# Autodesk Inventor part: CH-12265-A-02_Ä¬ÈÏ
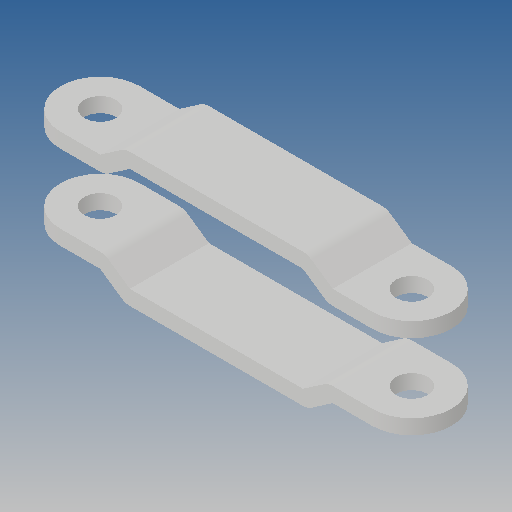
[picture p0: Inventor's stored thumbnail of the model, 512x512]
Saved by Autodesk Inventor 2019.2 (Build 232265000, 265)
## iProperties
Created: 2010-06
Part Number: CH-12265-A-02_Ä¬ÈÏ
Material: Ogólny
Document SubType Name: Modeling
Designer: CADENGINEERING4
Density: 1 g/cm^3
Appearance: Domyślna
Author: CADENGINEERING4
Revision Number: ÈÎºÎ
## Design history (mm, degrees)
feature "NONE"
feature "NONE:1"
node "Bryła1"
node "Bryła2"
